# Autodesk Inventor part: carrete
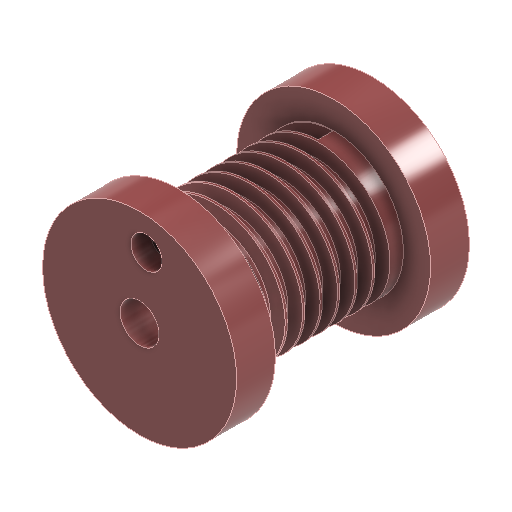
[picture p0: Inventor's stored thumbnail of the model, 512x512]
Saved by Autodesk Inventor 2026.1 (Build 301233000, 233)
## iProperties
Created: 2025-06
Part Number: carrete
Material: Genérico
Document SubType Name: Modeling
Designer: piero
Density: 1 g/cm^3
Appearance: Castaño
Author: piero
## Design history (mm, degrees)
sketch "Boceto1"
  geometry: C1 r 25 at (0, 0); C2 r 4 at (0, 0); C3 r 11 at (0, 0); 1 further point
  constraints: 3 centre point, 3 coincident
  dimensions: "d0" = 50 diameter of C1; "d3" = 8 diameter of C2; "d34" = 22 diameter of C3
extrude "Extrusión1" new body sketch "Boceto1" distance "d1" = 10; taper "d2" = 0 deg
sketch "Boceto5"
  geometry: C1 r 5 at (0, 0); C2 r 18 at (0, 0); 1 further point
  constraints: 2 centre point, 2 coincident
  dimensions: "d15" = 10 diameter of C1; "d16" = 36 diameter of C2
extrude "Extrusión5" join sketch "Boceto5" distance "d17" = 40; taper "d18" = 0 deg
sketch "Boceto6"
  geometry: C1 r 4 at (0, 0) reference; C2 r 25 at (0, 0); C3 r 4 at (0, 0); C4 r 5 at (0, 0) reference; C5 r 11 at (0, 0); 1 further point
  constraints: 3 centre point, 2 coincident
  dimensions: "d22" = 50 diameter of C2; "d30" = 8 diameter of C3; "d31" = 22 diameter of C5
extrude "Extrusión6" join sketch "Boceto6" distance "d23" = 10; taper "d24" = 0 deg
sketch "Boceto18"
  geometry: L1 (18, 10)-(18, 50) reference; L2 (18, 50)-(18, 46.125); L3 (18, 50)-(18, 46.125); L4 (18, 46.125)-(15, 46.901); L5 (15, 46.901)-(15, 49.224); L6 (15, 49.224)-(18, 50); C1 r 1.5 at (16.5, 48.063); 6 further points; 1 other entity
  constraints: 11 end point, 3 tangent, 1 centre point, 1 collinear, 1 equal length, 2 other
  dimensions: "d109" = 3 distance between parallel lines of L1 L5; "d110" = 3 diameter of C1; "d127" = 29 deg angle of L6 L4
feature "Bobina1" sketch "Boceto18" pitch "d99" = 4.5; turns "d101" = 8; dims "d100" = 35, "d102" = 0, angle "d103" = 90 deg, angle "d104" = 90 deg, "d105" = 0, "d106" = 0
sketch "Boceto19"
  geometry: L1 (0, 15)-(0, 18) reference; L2 (0, 18)-(0, 0); C1 r 1.75 at (1.75, 16.658); C2 r 5 at (0, 0) reference; C3 r 15 at (0, 0); 1 further point
  constraints: 2 centre point, 2 end point, 2 tangent, 1 coincident, 1 vertical
  dimensions: "d111" = 3.5 diameter of C1; "d114" = 30 diameter of C3
extrude "Extrusión13" cut sketch "Boceto19" distance "d112" = 13; taper "d113" = 0 deg
sketch "Boceto20"
  geometry: L1 (0, 15)-(0, 18); C1 r 1.75 at (-1.75, 16.658) reference; A1 r 15 centre (0, 0) between (0, 15) and (-1.567, 14.918); A2 r 18 centre (0, 0) between (0, 18) and (-0.614, 17.99); A3 r 1.75 centre (-1.75, 16.658) between (-1.567, 14.918) and (-0.614, 17.99); 4 further points
  constraints: 6 point on circle, 3 centre point, 3 coincident, 2 end point, 1 vertical
extrude "Extrusión14" join sketch "Boceto20" distance "d117" = 4.2; taper "d118" = 0 deg
sketch "Boceto24"
  geometry: C1 r 4 at (1.75, 16.658); C2 r 1.75 at (1.75, 16.658) reference; 1 further point
  constraints: 1 centre point, 1 concentric
  dimensions: "d130" = 8 diameter of C1
extrude "Extrusión16" cut sketch "Boceto24" distance "d128" = 5; taper "d129" = 0 deg
node "Sólido1"
